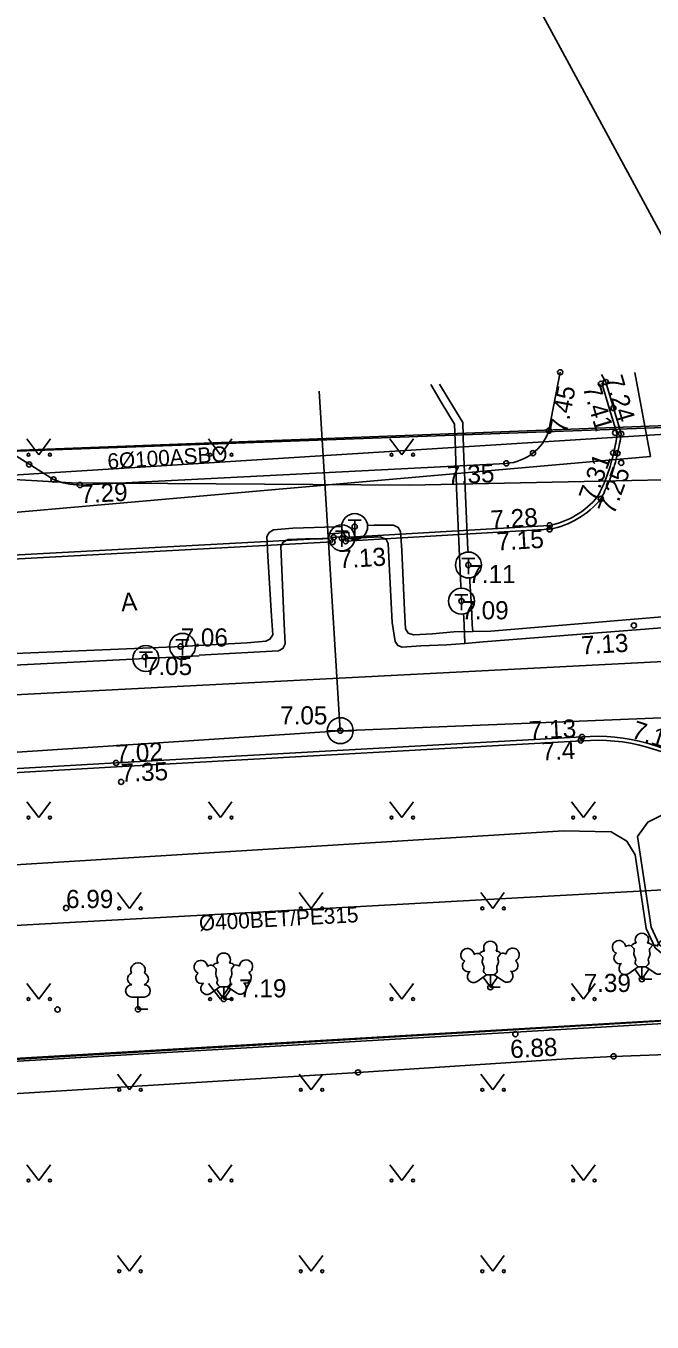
# Model space of a CAD drawing. Extents: x 473307 to 473719, y 6532843 to 6533381.
# Drawn here: x 473452.27 to 473476.41, y 6533254.01 to 6533304.01 of the extents above; entities that cross this region are included whole.
import ezdxf

# ---------------------------------------------------------------- set-up
doc = ezdxf.new("R2010")
doc.units = 0
for name, color, linetype in [('AED', 7, 'Continuous'), ('Default', 7, 'Continuous'), ('GTRASS', 7, 'Continuous'), ('HALJASTUS', 7, 'Continuous'), ('KORGUS', 7, 'Continuous'), ('KPKAABEL', 7, 'Continuous'), ('KTRASS', 7, 'Continuous'), ('KTRASS_TEKST', 7, 'Continuous'), ('MPKAABEL', 7, 'Continuous'), ('PIIR', 7, 'Continuous'), ('PUU', 7, 'Continuous'), ('SITRASS', 7, 'Continuous'), ('SITRASS_TEKST', 7, 'Continuous'), ('SKTRASS', 7, 'Continuous'), ('TEE', 7, 'Continuous'), ('TKAEV', 7, 'Continuous'), ('TTRASS', 7, 'Continuous'), ('VKAEV', 7, 'Continuous'), ('VTRASS', 7, 'Continuous')]:
    doc.layers.add(name, color=color, linetype=linetype)

# ---------------------------------------------------------------- blocks, each defined once
blk = doc.blocks.new('LEHTP1')
at = {"layer": 'Default'}
for p, q in [((0.48, 0.95), (-0.48, 0.95)), ((0, 0), (0, 0.95)), ((0.76, 0), (0, 0))]:
    blk.add_line(p, q, dxfattribs=at)
for centre, radius, start, end in [((0, 3.04), 0.554, 332.5799, 207.4201), ((-0.34, 2.345), 0.465, 109.02174, 253.14154), ((0.34, 2.345), 0.465, 286.85082, 70.98591), ((-0.475, 1.425), 0.475, 90.0016, 269.3953), ((0.475, 1.425), 0.475, 270.6047, 89.9984)]:
    blk.add_arc(centre, radius, start, end, dxfattribs=at)
blk = doc.blocks.new('VEKAEV')
at = {"layer": 'Default'}
blk.add_line((-1, 0), (1, 0), dxfattribs=at)
blk.add_circle((0, 0), 1, dxfattribs=at)
blk = doc.blocks.new('SOKAEV')
at = {"layer": 'Default'}
for p, q in [((-0.5, 0.5), (0.5, 0.5)), ((0, -0.7), (0, 0.5))]:
    blk.add_line(p, q, dxfattribs=at)
blk.add_circle((0, 0), 1, dxfattribs=at)
blk = doc.blocks.new('MURU')
at = {"layer": 'Default'}
for p, q in [((-0.927, 1.213), (0, 0)), ((0, 0), (0.891, 1.213))]:
    blk.add_line(p, q, dxfattribs=at)
for centre in [(-0.802, 0), (0.856, 0)]:
    blk.add_circle(centre, 0.11, dxfattribs=at)
blk = doc.blocks.new('LEHTP3')
at = {"layer": 'Default'}
for p, q in [((-1.02, 0.44), (-0.3, 0.95)), ((0, 0), (-0.55, 0.77)), ((-0.3, 0.95), (0.29, 0.95)), ((0, 0), (0, 0.95)), ((0, 0), (0.54, 0.78)), ((0.76, 0), (0, 0)), ((0.29, 0.95), (1.01, 0.46))]:
    blk.add_line(p, q, dxfattribs=at)
for points in [[(-0.825, 2.575), (-0.62, 2.37), (-0.59, 2.31), (-0.59, 2.2), (-0.62, 2.02), (-0.62, 1.93), (-0.58, 1.77), (-0.5, 1.59), (-0.48, 1.5), (-0.49, 1.41), (-0.52, 1.28), (-0.52, 1.22), (-0.48, 1.14), (-0.43, 1.08), (-0.3, 0.95)], [(0.808, 2.603), (0.62, 2.37), (0.59, 2.31), (0.59, 2.2), (0.62, 2.02), (0.63, 1.93), (0.59, 1.77), (0.51, 1.59), (0.49, 1.5), (0.5, 1.41), (0.53, 1.28), (0.53, 1.22), (0.49, 1.14), (0.44, 1.08), (0.3, 0.95)]]:
    blk.add_lwpolyline(points, dxfattribs=at)
for centre, radius, start, end in [((0, 3.04), 0.512, 90.00126, 211.01588), ((0, 3.04), 0.512, 328.98412, 89.99874), ((1.721, 2.506), 0.512, 55.52204, 176.53666), ((-1.767, 2.474), 0.512, 125.53894, 246.55356), ((-1.711, 1.64), 0.448, 125.46665, 288.53492), ((-1.767, 2.474), 0.512, 4.5218, 125.53642), ((-0.994, 2.209), 0.403, 65.23821, 130.74121), ((-0.475, 2.375), 0.403, 84.79647, 150.29947), ((0.475, 2.375), 0.403, 34.38566, 95.20353), ((0.953, 2.227), 0.403, 50.31726, 111.13512), ((1.68, 1.671), 0.448, 252.52354, 55.59181), ((1.721, 2.506), 0.512, 294.50491, 55.51952), ((-1.292, 0.828), 0.475, 125.53768, 305.53661), ((1.277, 0.852), 0.475, 235.52186, 55.52078)]:
    blk.add_arc(centre, radius, start, end, dxfattribs=at)

msp = doc.modelspace()

# ---------------------------------------------------------------- linework, layer by layer
at = {"layer": 'AED'}
msp.add_lwpolyline([(473447.226, 6533263.902), (473496.402, 6533266.794), (473497.156, 6533266.092)], dxfattribs=at)
at = {"layer": 'GTRASS'}
msp.add_lwpolyline([(473352.971, 6533276.721), (473360.98, 6533278.32), (473373.58, 6533279.142), (473409.861, 6533281.542), (473476.35, 6533287.4), (473475.752, 6533290.633)], dxfattribs=at)
at = {"layer": 'KORGUS'}
for centre in [(473472.874, 6533290.647), (473474.44, 6533290.198), (473474.627, 6533290.268), (473474.924, 6533289.269), (473472.438, 6533288.395), (473474.988, 6533288.313), (473475.221, 6533288.272), (473471.822, 6533287.527), (473474.917, 6533287.536), (473475.082, 6533287.526), (473452.394, 6533287.091), (473470.793, 6533287.133), (473475.224, 6533287.155), (473453.333, 6533286.513), (473454.353, 6533286.296), (473474.442, 6533285.767), (473464.948, 6533284.693), (473472.469, 6533284.742), (473464.134, 6533284.278), (473464.453, 6533284.247), (473472.462, 6533284.589), (473464.095, 6533284.101), (473464.599, 6533284.132), (473469.333, 6533283.212), (473469.064, 6533281.817), (473475.715, 6533280.879), (473456.858, 6533279.665), (473458.237, 6533280.068), (473464.393, 6533276.821), (473473.666, 6533276.445), (473473.714, 6533276.578), (473455.75, 6533275.577), (473455.943, 6533274.844), (473453.82, 6533269.979), (473476.024, 6533267.233), (473470.179, 6533266.925), (473459.898, 6533266.468), (473453.492, 6533266.064), (473456.592, 6533266.072), (473471.144, 6533265.117), (473474.928, 6533264.258), (473465.077, 6533263.639)]:
    msp.add_circle(centre, 0.1, dxfattribs=at)
at = {"layer": 'KPKAABEL'}
for points in [[(473546.224, 6533294.769), (473547.496, 6533292.321), (473547.372, 6533291.903), (473543.34, 6533286.034), (473541.318, 6533282.133), (473539.554, 6533279.533), (473538.159, 6533277.421), (473531.307, 6533275.958), (473516.917, 6533275.473), (473488.292, 6533273.67), (473476.815, 6533273.569), (473476.248, 6533273.293), (473475.851, 6533272.737), (473475.958, 6533272.062), (473476.382, 6533269.243), (473476.692, 6533268.57), (473477.067, 6533268.256), (473477.763, 6533268.245)], [(473353.442, 6533266.475), (473356.914, 6533266.999), (473362.351, 6533267.084), (473370.408, 6533267.159), (473390.326, 6533268.234), (473405.754, 6533269.007), (473418.445, 6533269.933), (473432.973, 6533270.56), (473448.952, 6533271.468), (473462.862, 6533272.322), (473472.995, 6533272.957), (473474.843, 6533272.925), (473475.447, 6533272.555), (473475.76, 6533272.032), (473476.188, 6533269.185), (473476.53, 6533268.446), (473476.993, 6533268.058), (473477.779, 6533268.045)]]:
    msp.add_lwpolyline(points, dxfattribs=at)
at = {"layer": 'KTRASS'}
msp.add_line((473447.677, 6533269.084), (473485.906, 6533271.173), dxfattribs=at)
at = {"layer": 'MPKAABEL'}
for points in [[(473413.879, 6533285.041), (473421.046, 6533285.725), (473435.898, 6533286.846), (473444.295, 6533287.087), (473446.061, 6533286.839), (473454.024, 6533286.382), (473467.054, 6533286.286), (473479.314, 6533286.552), (473485.038, 6533287.191), (473485.942, 6533287.951), (473486.56, 6533287.104), (473507.071, 6533288.073), (473521.921, 6533288.182), (473522.937, 6533289.965), (473525.948, 6533290.824), (473539.287, 6533291.718)], [(473444.295, 6533287.087), (473446.061, 6533286.839), (473454.024, 6533286.382), (473467.054, 6533286.286), (473479.314, 6533286.552), (473485.038, 6533287.191), (473485.942, 6533287.951)], [(473495.18, 6533225.875), (473494.734, 6533234.807), (473494.611, 6533236.968), (473494.449, 6533239.274), (473493.992, 6533245.232), (473493.386, 6533253.252), (473492.746, 6533261.702), (473492.562, 6533264.044), (473492.519, 6533264.695), (473492.434, 6533264.849), (473492.337, 6533264.926), (473492.01, 6533264.929), (473486.235, 6533264.685), (473483.652, 6533264.576), (473480.112, 6533264.424), (473477.661, 6533264.35), (473474.928, 6533264.258), (473473.125, 6533264.162), (473465.077, 6533263.639), (473448.214, 6533262.592), (473437.85, 6533261.982), (473429.907, 6533261.511), (473420.42, 6533260.861)]]:
    msp.add_lwpolyline(points, dxfattribs=at)
at = {"layer": 'PIIR'}
for points in [[(473449.76, 6533380.885), (473433.52, 6533372.29), (473447.71, 6533347.37), (473454.72, 6533346.94), (473461.17, 6533334.49), (473476.21, 6533307.58), (473471.79, 6533305.18), (473480.69, 6533288.74), (473430.17, 6533286.8), (473426.19, 6533307.67), (473415.91, 6533326.36), (473400.95, 6533323.6), (473392.61, 6533364.11), (473394.06, 6533370.53), (473399.03, 6533371.95), (473403.75, 6533374.68), (473415.377, 6533380.885)], [(473306.698, 6533269.314), (473318.22, 6533273.04), (473319.15, 6533273.32), (473325.84, 6533274.58), (473345.31, 6533277.99), (473387.78, 6533284.78), (473409.45, 6533285.94), (473429.73, 6533289.19), (473430.17, 6533286.8), (473480.73, 6533288.66), (473545.58, 6533292.4), (473585.1, 6533294.7), (473599.09, 6533295.91), (473601.54, 6533272.81), (473586.5, 6533271.93), (473496.37, 6533266.79), (473372.23, 6533259.41), (473356.5, 6533258.46), (473354.97, 6533266.17), (473326.61, 6533261.28), (473306.698, 6533254.866)]]:
    msp.add_lwpolyline(points, dxfattribs=at)
for points in [[(473480.69, 6533288.74), (473471.79, 6533305.18), (473476.25, 6533307.51), (473476.21, 6533307.58), (473461.17, 6533334.49), (473465.17, 6533335.3), (473485.24, 6533339.32), (473504.35, 6533345.55), (473520.75, 6533316.46), (473536.31, 6533310.52), (473545.58, 6533292.4), (473480.73, 6533288.66)], [(473383.26, 6533220.83), (473372.23, 6533259.41), (473496.37, 6533266.79), (473499.84, 6533206.38), (473559.2, 6533209.37), (473561.43, 6533165.2), (473601.75, 6533167.04), (473607.56, 6533132.38), (473611.09, 6533109.85), (473618.6, 6533063.82), (473572.63, 6533056.43), (473548.5, 6533028.91), (473478.82, 6533017), (473455.33, 6533045.76), (473432.18, 6533083.36), (473429.59, 6533087.74), (473409.64, 6533129), (473385.1, 6533214.25), (473398.68, 6533216.8), (473398.11, 6533224.3)]]:
    msp.add_lwpolyline(points, close=True, dxfattribs=at)
at = {"layer": 'SITRASS'}
msp.add_line((473421.469, 6533284.782), (473480.248, 6533288.472), dxfattribs=at)
at = {"layer": 'SKTRASS'}
msp.add_lwpolyline([(473431.814, 6533277.181), (473489.624, 6533280.143)], dxfattribs=at)
at = {"layer": 'TEE'}
msp.add_line((473474.627, 6533290.268), (473474.467, 6533290.557), dxfattribs=at)
for points in [[(473472.438, 6533288.395), (473472.874, 6533290.647)], [(473475.221, 6533288.272), (473474.924, 6533289.269), (473474.627, 6533290.268)], [(473475.068, 6533288.26), (473474.78, 6533289.226), (473474.483, 6533290.225)], [(473449.242, 6533289.077), (473453.333, 6533286.513)], [(473454.353, 6533286.296), (473470.793, 6533287.133)], [(473383.747, 6533279.941), (473388.989, 6533280.23), (473395.414, 6533280.514), (473421.395, 6533281.942), (473450.313, 6533283.513), (473463.939, 6533284.243), (473463.932, 6533284.415), (473464.724, 6533284.472), (473464.737, 6533284.29), (473472.444, 6533284.738)], [(473383.756, 6533279.791), (473388.996, 6533280.08), (473395.421, 6533280.364), (473421.403, 6533281.792), (473450.321, 6533283.363), (473464.095, 6533284.101), (473464.088, 6533284.276), (473464.585, 6533284.312), (473464.599, 6533284.132), (473472.462, 6533284.589)], [(473372.879, 6533270.945), (473396.372, 6533272.18), (473425.485, 6533273.829), (473455.75, 6533275.577), (473473.714, 6533276.578)], [(473372.901, 6533270.796), (473396.38, 6533272.03), (473425.493, 6533273.679), (473455.759, 6533275.427), (473473.724, 6533276.428)]]:
    msp.add_lwpolyline(points, dxfattribs=at)
msp.add_lwpolyline([(473396.254, 6533260.803), (473411.137, 6533261.686), (473430.688, 6533262.81), (473450.64, 6533263.99), (473471.14, 6533265.187), (473496.199, 6533266.651), (473497.903, 6533237.901), (473499.304, 6533214.158), (473499.292, 6533213.775), (473499.248, 6533213.313), (473499.158, 6533212.95), (473498.962, 6533212.533), (473498.665, 6533212.147), (473498.271, 6533211.83), (473497.797, 6533211.622), (473497.201, 6533211.492), (473496.826, 6533211.447), (473473.837, 6533210.118), (473452.83, 6533208.91), (473434.945, 6533207.846), (473416.821, 6533206.798), (473399.468, 6533205.756), (473398.532, 6533221.8), (473397.351, 6533241.472)], close=True, dxfattribs=at)
for centre, radius, start, end in [((473470.669, 6533288.998), 1.869, 273.8086, 341.1803), ((473468.596, 6533289.121), 6.53, 346.1652, 352.4248), ((473468.596, 6533289.121), 6.68, 346.189, 352.7016), ((473468.699, 6533288.852), 6.369, 331.8796, 348.2849), ((473468.699, 6533288.852), 6.519, 331.7523, 348.2605), ((473454.429, 6533289.157), 2.862, 247.493, 268.4863), ((473471.859, 6533287.856), 3.172, 280.6269, 320.7885), ((473471.859, 6533287.856), 3.322, 280.46, 321.0411), ((473474.313, 6533269.411), 7.192, 54.4596, 94.7822), ((473474.313, 6533269.411), 7.042, 54.4517, 94.7991)]:
    msp.add_arc(centre, radius, start, end, dxfattribs=at)
at = {"layer": 'TTRASS'}
for points in [[(473467.886, 6533290.171), (473468.287, 6533289.491), (473468.802, 6533288.65), (473468.83, 6533287.664), (473468.871, 6533286.182), (473469.047, 6533282.401), (473469.055, 6533282.314)], [(473468.216, 6533290.19), (473468.593, 6533289.569), (473469.113, 6533288.706), (473469.15, 6533287.699), (473469.206, 6533286.17), (473469.315, 6533283.802), (473469.319, 6533283.728)], [(473465.434, 6533284.738), (473465.694, 6533284.749), (473466.447, 6533284.755), (473466.627, 6533284.664), (473466.716, 6533284.507), (473466.765, 6533283.771), (473466.869, 6533281.468), (473466.908, 6533280.755), (473467.012, 6533280.584), (473467.214, 6533280.516), (473467.95, 6533280.563), (473468.773, 6533280.628), (473469.508, 6533280.644), (473470.199, 6533280.658), (473482.174, 6533281.662), (473494.129, 6533282.6), (473506.198, 6533283.452), (473518.136, 6533284.378), (473530.121, 6533285.357), (473537.652, 6533285.985)], [(473464.803, 6533284.254), (473465.161, 6533284.264), (473465.95, 6533284.297), (473466.168, 6533284.201), (473466.237, 6533284.046), (473466.282, 6533283.258), (473466.388, 6533280.988), (473466.509, 6533280.266), (473466.615, 6533280.106), (473466.776, 6533280.048), (473467.501, 6533280.094), (473468.5, 6533280.134), (473469.195, 6533280.189), (473469.899, 6533280.246), (473481.865, 6533281.193), (473493.907, 6533282.185), (473505.831, 6533283.097), (473517.791, 6533284.039), (473529.805, 6533284.958), (473537.412, 6533285.531)], [(473458.884, 6533280.104), (473460.804, 6533280.216), (473461.525, 6533280.27), (473461.679, 6533280.345), (473461.787, 6533280.516), (473461.735, 6533281.242), (473461.599, 6533283.551), (473461.558, 6533284.314), (473461.649, 6533284.465), (473461.819, 6533284.568), (473462.56, 6533284.638), (473464.214, 6533284.689), (473464.445, 6533284.699)], [(473458.948, 6533279.729), (473461.287, 6533279.861), (473462.012, 6533279.905), (473462.183, 6533279.99), (473462.262, 6533280.169), (473462.226, 6533280.927), (473462.104, 6533283.934), (473462.195, 6533284.092), (473462.377, 6533284.201), (473463.056, 6533284.216), (473463.726, 6533284.224), (473463.954, 6533284.231)], [(473469.384, 6533282.731), (473469.394, 6533282.572), (473469.449, 6533281.605), (473469.474, 6533280.92), (473469.508, 6533280.644)], [(473469.147, 6533281.32), (473469.16, 6533281.183), (473469.18, 6533280.552), (473469.195, 6533280.189)], [(473353.109, 6533273.732), (473359.448, 6533274.47), (473364.817, 6533275.003), (473364.615, 6533277.039), (473366.54, 6533277.239), (473367.243, 6533277.321), (473369.251, 6533277.556), (473369.416, 6533275.425), (473378.385, 6533276.161), (473384.467, 6533276.364), (473409.656, 6533277.734), (473433.656, 6533279.045), (473458.306, 6533280.074), (473458.884, 6533280.111)], [(473353.128, 6533273.318), (473360.095, 6533274.113), (473365.18, 6533274.509), (473364.98, 6533276.522), (473366.064, 6533276.63), (473366.654, 6533276.702), (473368.689, 6533276.951), (473368.851, 6533274.868), (473378.363, 6533275.607), (473384.321, 6533275.885), (473408.317, 6533277.054), (473432.298, 6533278.353), (473456.899, 6533279.604), (473458.957, 6533279.712)]]:
    msp.add_lwpolyline(points, dxfattribs=at)
at = {"layer": 'VTRASS'}
for points in [[(473463.585, 6533289.919), (473464.393, 6533276.821)], [(473353.303, 6533269.506), (473365.999, 6533272.186), (473379.745, 6533270.923), (473385.029, 6533271.056), (473412.227, 6533273.37), (473464.393, 6533276.821), (473499.973, 6533278.249), (473517.192, 6533279.473), (473556.042, 6533281.885), (473612.816, 6533284.928)]]:
    msp.add_lwpolyline(points, dxfattribs=at)

# ---------------------------------------------------------------- block references
at = {"layer": 'HALJASTUS', "xscale": 0.5, "yscale": 0.5}
for p in [(473452.771, 6533287.467), (473459.771, 6533287.467), (473466.771, 6533287.467), (473452.771, 6533273.467), (473459.771, 6533273.467), (473466.771, 6533273.467), (473473.771, 6533273.467), (473456.271, 6533269.967), (473463.271, 6533269.967), (473470.271, 6533269.967), (473452.771, 6533266.467), (473459.771, 6533266.467), (473466.771, 6533266.467), (473473.771, 6533266.467), (473456.271, 6533262.967), (473463.271, 6533262.967), (473470.271, 6533262.967), (473452.771, 6533259.467), (473459.771, 6533259.467), (473466.771, 6533259.467), (473473.771, 6533259.467), (473456.271, 6533255.967), (473463.271, 6533255.967), (473470.271, 6533255.967)]:
    msp.add_blockref('MURU', p, dxfattribs=at)
at = {"layer": 'PUU', "xscale": 0.5, "yscale": 0.5}
for name, p in [('LEHTP3', (473476.024, 6533267.233)), ('LEHTP3', (473470.179, 6533266.925)), ('LEHTP1', (473456.592, 6533266.072)), ('LEHTP3', (473459.898, 6533266.468))]:
    msp.add_blockref(name, p, dxfattribs=at)
at = {"layer": 'TKAEV', "xscale": 0.5, "yscale": 0.5}
for p in [(473464.453, 6533284.262), (473464.948, 6533284.693), (473469.333, 6533283.212), (473469.066, 6533281.814), (473458.306, 6533280.074), (473456.899, 6533279.604)]:
    msp.add_blockref('SOKAEV', p, dxfattribs=at)
at = {"layer": 'VKAEV', "xscale": 0.5, "yscale": 0.5}
msp.add_blockref('VEKAEV', (473464.393, 6533276.821), dxfattribs=at)

# ---------------------------------------------------------------- texts
at = {"layer": 'KORGUS'}
for s, rotation, p in [('7.24', 286.5766, (473474.584, 6533290.413)), ('7.45', 79.0406, (473473.125, 6533288.262)), ('7.41', 286.5766, (473473.737, 6533290.062)), ('7.31', 70, (473474.222, 6533285.625)), ('7.35', 2.9145, (473468.532, 6533286.317)), ('7.25', 70.0064, (473474.953, 6533285.125)), ('7.29', 2.9145, (473454.389, 6533285.597)), ('7.28', 3.3269, (473470.206, 6533284.61)), ('7.15', 3.3269, (473470.439, 6533283.77)), ('7.13', 3.4696, (473464.354, 6533283.082)), ('7.13', 3.4696, (473473.702, 6533279.759)), ('7.13', 2.7409, (473471.683, 6533276.481)), ('7.15', 342.2877, (473475.58, 6533276.556)), ('7.02', 3.3053, (473455.75, 6533275.577)), ('7.4', 2.7409, (473472.168, 6533275.672)), ('7.35', 2.2319, (473455.943, 6533274.844)), ('6.88', 3, (473470.961, 6533264.186))]:
    msp.add_text(s, height=0.7, rotation=rotation, dxfattribs=at).set_placement(p)
for s, p in [('7.11', (473469.333, 6533282.512)), ('7.09', (473469.064, 6533281.117)), ('7.06', (473458.237, 6533280.068)), ('7.05', (473456.858, 6533278.965)), ('7.05', (473462.074, 6533277.063)), ('6.99', (473453.82, 6533269.979)), ('7.39', (473473.777, 6533266.741)), ('7.19', (473460.495, 6533266.534))]:
    msp.add_text(s, height=0.7, dxfattribs=at).set_placement(p)
at = {"layer": 'KTRASS_TEKST'}
msp.add_text('%%C400BET/PE315', height=0.6, rotation=3.1268, dxfattribs=at).set_placement((473458.96, 6533269.1))
at = {"layer": 'SITRASS_TEKST'}
msp.add_text('6%%c100ASBO', height=0.6, rotation=3.6565, dxfattribs=at).set_placement((473455.433, 6533286.911))
at = {"layer": 'TEE'}
msp.add_text('A', height=0.7, rotation=3.6175, dxfattribs=at).set_placement((473455.957, 6533281.423))

doc.saveas('drawing.dxf')
